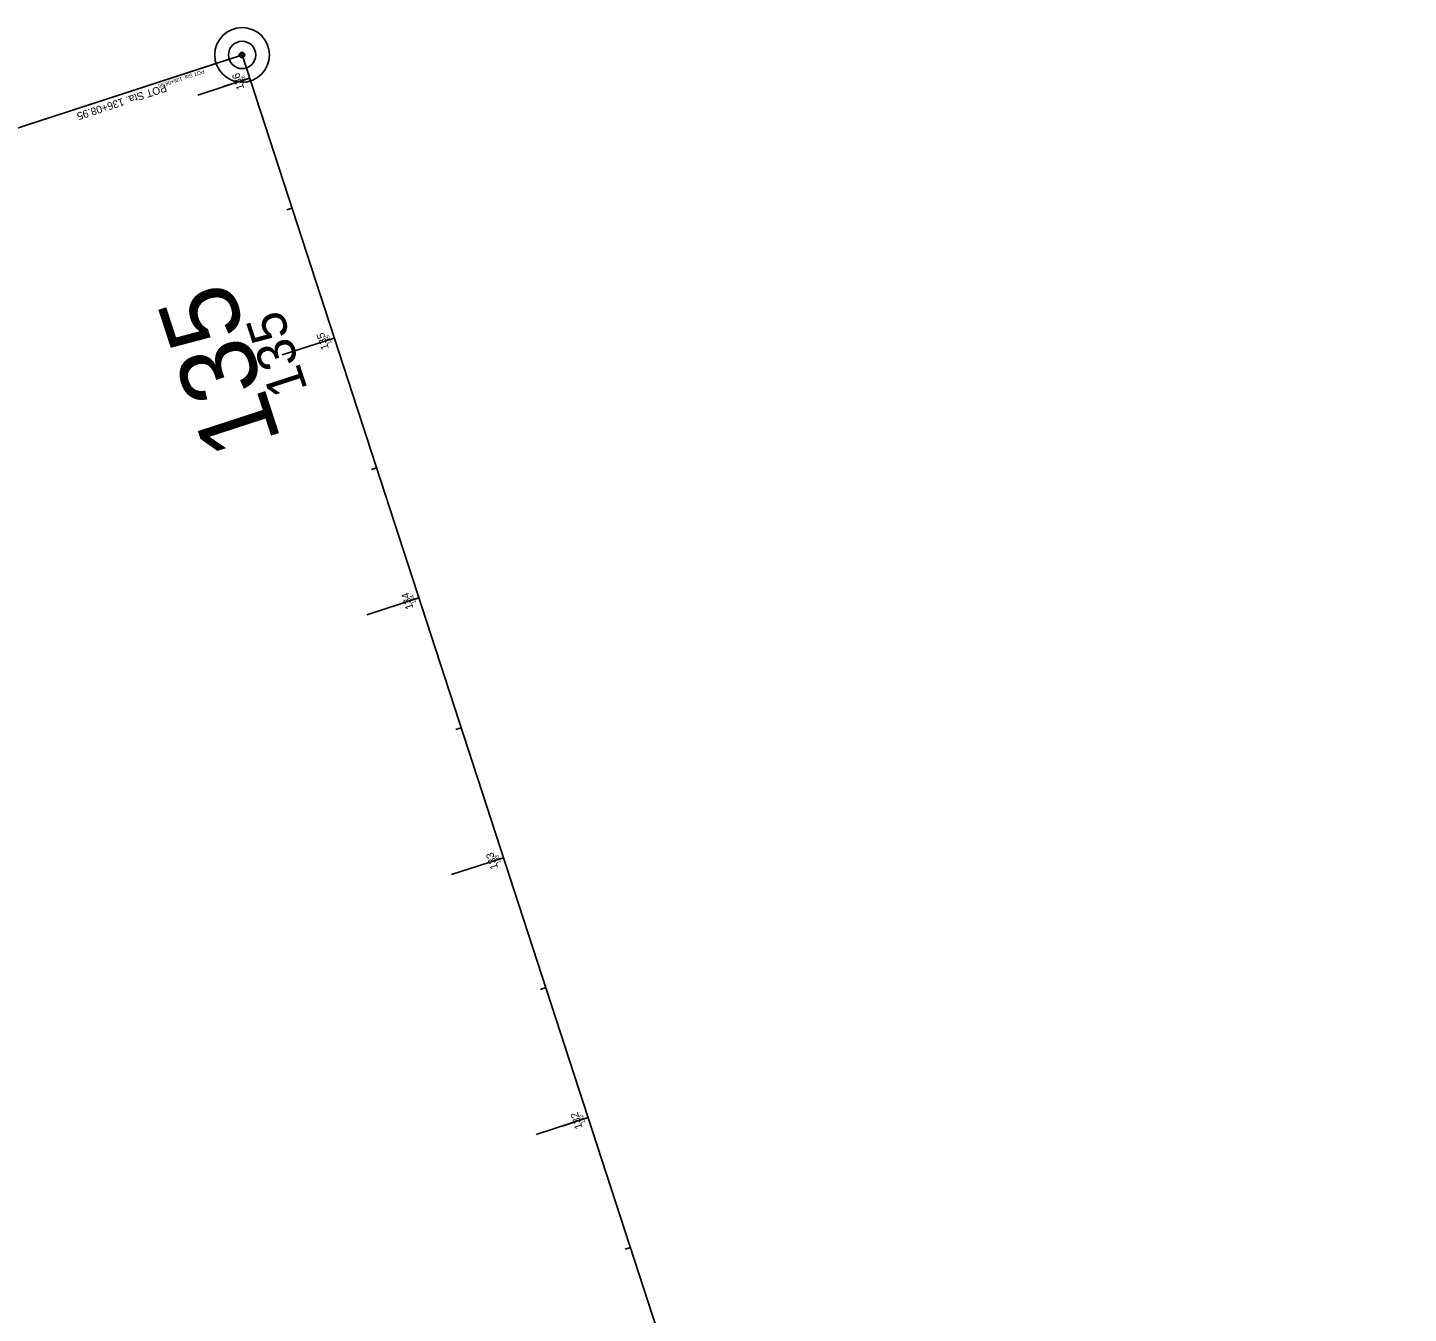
# Model space of a CAD drawing. Extents: x 1794716 to 1797874, y 325521 to 329174.
# Drawn here: x 1795669 to 1796174, y 328704 to 329174 of the extents above; entities that cross this region are included whole.
import ezdxf

# ---------------------------------------------------------------- set-up
doc = ezdxf.new("R2010")
doc.units = 0
for name, color, linetype in [('GE_P_CL_10', 7, 'Continuous'), ('GE_P_CL_100', 7, 'Continuous'), ('GE_P_CL_20', 7, 'Continuous'), ('GE_P_CL_200', 7, 'Continuous'), ('GE_P_CL_25', 7, 'Continuous'), ('RW_X_CL_20', 7, 'Continuous')]:
    doc.layers.add(name, color=color, linetype=linetype)

msp = doc.modelspace()

# ---------------------------------------------------------------- linework, layer by layer
at = {"layer": 'GE_P_CL_10'}
for p, q in [((1795746.56, 329164.02), (1795712.29, 329152.86)), ((1796173.82, 327853.48), (1795747.03, 329164.17)), ((1795749.8, 329155.66), (1795748.85, 329155.35)), ((1795765.29, 329108.12), (1795764.33, 329107.81)), ((1795780.77, 329060.58), (1795779.82, 329060.27)), ((1795796.25, 329013.03), (1795795.3, 329012.72)), ((1795811.73, 328965.49), (1795810.78, 328965.18)), ((1795827.21, 328917.95), (1795826.26, 328917.64)), ((1795842.69, 328870.41), (1795841.74, 328870.1)), ((1795858.17, 328822.86), (1795857.22, 328822.55)), ((1795873.65, 328775.32), (1795872.7, 328775.01)), ((1795889.13, 328727.78), (1795888.18, 328727.47))]:
    msp.add_line(p, q, dxfattribs=at)
msp.add_circle((1795747.03, 329164.17), 0.5, dxfattribs=at)
at = {"layer": 'GE_P_CL_100'}
for p, q in [((1795742.28, 329162.63), (1795447.11, 329066.51)), ((1796173.82, 327853.48), (1795747.03, 329164.17)), ((1795749.8, 329155.66), (1795740.3, 329152.57)), ((1795780.77, 329060.58), (1795771.26, 329057.48)), ((1795811.73, 328965.49), (1795802.22, 328962.4)), ((1795842.69, 328870.41), (1795833.18, 328867.31)), ((1795873.65, 328775.32), (1795864.14, 328772.22))]:
    msp.add_line(p, q, dxfattribs=at)
msp.add_circle((1795747.03, 329164.17), 5, dxfattribs=at)
at = {"layer": 'GE_P_CL_20'}
for p, q in [((1796173.82, 327853.48), (1795747.03, 329164.17)), ((1795749.8, 329155.66), (1795747.9, 329155.04)), ((1795765.29, 329108.12), (1795763.38, 329107.5)), ((1795780.77, 329060.58), (1795778.86, 329059.96)), ((1795796.25, 329013.03), (1795794.35, 329012.42)), ((1795811.73, 328965.49), (1795809.83, 328964.87)), ((1795827.21, 328917.95), (1795825.31, 328917.33)), ((1795842.69, 328870.41), (1795840.79, 328869.79)), ((1795858.17, 328822.86), (1795856.27, 328822.24)), ((1795873.65, 328775.32), (1795871.75, 328774.7)), ((1795889.13, 328727.78), (1795887.23, 328727.16))]:
    msp.add_line(p, q, dxfattribs=at)
at = {"layer": 'GE_P_CL_200'}
for p, q in [((1795737.52, 329161.08), (1795147.19, 328968.86)), ((1796173.82, 327853.48), (1795747.03, 329164.17)), ((1795749.8, 329155.66), (1795730.79, 329149.47)), ((1795780.77, 329060.58), (1795761.75, 329054.38)), ((1795811.73, 328965.49), (1795792.71, 328959.3)), ((1795842.69, 328870.41), (1795823.67, 328864.21)), ((1795873.65, 328775.32), (1795854.63, 328769.13))]:
    msp.add_line(p, q, dxfattribs=at)
msp.add_circle((1795747.03, 329164.17), 10, dxfattribs=at)
at = {"layer": 'GE_P_CL_25'}
msp.add_line((1795746.08, 329163.86), (1795677.54, 329141.55), dxfattribs=at)
msp.add_circle((1795747.03, 329164.17), 1, dxfattribs=at)
at = {"layer": 'RW_X_CL_20'}
msp.add_line((1796173.82, 327853.48), (1795747.03, 329164.17), dxfattribs=at)

# ---------------------------------------------------------------- texts
at = {"layer": 'GE_P_CL_10'}
for s, rotation, p in [('POT Sta. 136+08.95', 198.0361, (1795732.99, 329158.86)), ('136', 108.0361, (1795748.84, 329153.78)), ('135', 108.0361, (1795779.8, 329058.7)), ('134', 108.0361, (1795810.76, 328963.63)), ('133', 108.0361, (1795841.72, 328868.53)), ('132', 108.0361, (1795872.68, 328773.46))]:
    msp.add_text(s, height=1.4, rotation=rotation, dxfattribs=at).set_placement(p)
at = {"layer": 'GE_P_CL_100'}
msp.add_text('135', height=14, rotation=108.0361, dxfattribs=at).set_placement((1795771.09, 329041.84))
at = {"layer": 'GE_P_CL_20'}
for s, p in [('136', (1795747.87, 329151.91)), ('135', (1795778.83, 329056.83)), ('134', (1795809.78, 328961.77)), ('133', (1795840.76, 328866.65)), ('132', (1795871.71, 328771.59))]:
    msp.add_text(s, height=2.8, rotation=108.0361, dxfattribs=at).set_placement(p)
at = {"layer": 'GE_P_CL_200'}
msp.add_text('135', height=28, rotation=108.0361, dxfattribs=at).set_placement((1795761.42, 329023.1))
at = {"layer": 'GE_P_CL_25'}
msp.add_text('POT Sta. 136+08.95', height=2.8, rotation=198.0361, dxfattribs=at).set_placement((1795718.94, 329153.55))

doc.saveas('drawing.dxf')
